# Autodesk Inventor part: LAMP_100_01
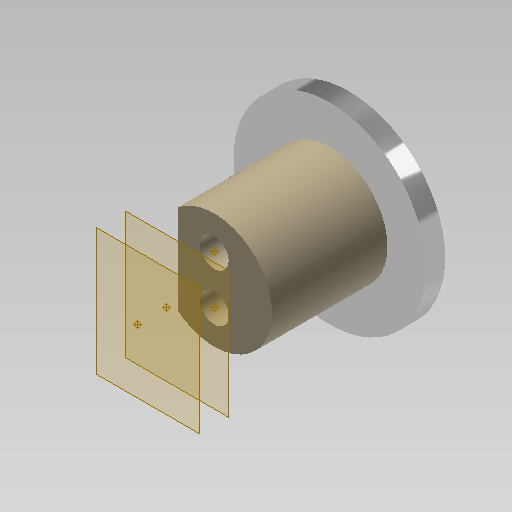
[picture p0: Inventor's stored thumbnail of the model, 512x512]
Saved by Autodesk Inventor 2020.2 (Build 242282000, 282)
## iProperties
GlobalPropertyList: <PropertyList/>
Manager: www.cadconsulting.pl
Company: Fabian Stasiak CAD Consulting
Created: 2014-09
Part Number: LAMP_100_01
Material: Ogólny
Document SubType Name: Modeling
Designer: F.Stasiak
Density: 1 g/cm^3
Appearance: Beżowa
Catalog Web Link: www.expertbooks.pl
Author: F.Stasiak
Subject: Zbiór ćwiczeń. Autodesk Inventor 2020. Kurs Professional
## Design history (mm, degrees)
sketch "Szkic1"
  geometry: C1 r 10 at (0, 0); 1 further point
  constraints: 1 centre point, 1 coincident
  dimensions: "d0" = 20 diameter of C1
extrude "Wyciągnięcie proste1" new body sketch "Szkic1" distance "d1" = 2; taper "d2" = 0 deg
sketch "Szkic2"
  geometry: C1 r 6 at (0, 0); 1 further point
  constraints: 1 centre point, 1 coincident
  dimensions: "d3" = 12 diameter of C1
extrude "Wyciągnięcie proste2" join sketch "Szkic2" distance "d4" = 12; taper "d5" = 0 deg
sketch "Szkic3"
  geometry: L1 (0, -2.5)-(0, 2.5); C1 r 1.5 at (0, -2.5); C2 r 1.5 at (0, 2.5); 2 further points
  constraints: 2 centre point, 2 end point, 1 coincident, 1 midpoint, 1 vertical
  dimensions: "d6" = 3 diameter of C1; "d7" = 3 diameter of C2; "d8" = 5 distance of L1.start L1.end
extrude "Wyciągnięcie proste3" cut sketch "Szkic3" distance "d9" = 5; taper "d10" = 0 deg
node "Płaszczyzna konstrukcyjna1"
sketch "Szkic4"
  geometry: L1 (9.27, 2)-(9.27, 0) reference; L2 (9.27, 0)-(-9.27, 0) reference; L3 (-9.27, 0)-(-9.27, 2) reference; L4 (-9.27, 2)-(-4.684, 2) reference; L5 (-4.684, 2)-(-4.684, 14) reference; L6 (-4.684, 14)-(4.684, 14) reference; L7 (4.684, 14)-(4.684, 2) reference; L8 (4.684, 2)-(9.27, 2) reference; L9 (-4.684, 8)-(4.684, 8); 1 further point
  constraints: 2 end point, 2 midpoint
extrude "Wyciągnięcie proste4" cut sketch "Szkic4" extent not by distance; stored distance "d12" = 5; taper "d13" = 0 deg
sketch "Szkic5"
  geometry: L1 (10, -2.5)-(10, 2.5); L2 (14, 4.684)-(14, -4.684) reference; C1 r 2 at (10, -2.5); C2 r 2 at (10, 2.5); 3 further points
  constraints: 2 centre point, 2 end point, 2 midpoint, 1 equal radius, 1 horizontal alignment, 1 vertical
  dimensions: "d14" = 4 diameter of C2; "d15" = 5 distance of L1.start L1.end; "d16" = 4 distance from line of L1.end L2
extrude "Wyciągnięcie proste5" cut sketch "Szkic5" distance "d17" = 0.5; taper "d18" = 0 deg
sketch "Szkic6"
  geometry: L1 (0.375, 1.56)-(-0.225, 1.56); L2 (-0.225, 1.56)-(-0.225, -1.44); L3 (-0.225, -1.44)-(0.375, -1.44); L4 (0.375, -1.44)-(0.375, 1.56); L5 (0.375, 1.56)-(-0.225, -1.44); L6 (-0.225, 1.56)-(0.375, -1.44); L7 (1.575, 0.36)-(-1.425, 0.36); L8 (-1.425, 0.36)-(-1.425, -0.24); L9 (-1.425, -0.24)-(1.575, -0.24); L10 (1.575, -0.24)-(1.575, 0.36); L11 (1.575, 0.36)-(-1.425, -0.24); L12 (-1.425, 0.36)-(1.575, -0.24); C1 r 2 at (0.075, 0.06) reference; 3 further points
  constraints: 24 end point, 5 midpoint, 4 parallel, 2 horizontal, 2 perpendicular, 1 coincident
  dimensions: "d21" = 0.6 distance of L3.end L2.end; "d22" = 3 distance of L2.end L1.end; "d19" = 3 distance of L9.end L8.end (= d22); "d20" = 0.6 distance of L8.end L7.end
extrude "Wyciągnięcie proste6" cut sketch "Szkic6" taper "d24" = -5 deg; distance "d25" = 1
mirror "Odbicie lustrzane1"
sketch "Szkic7"
  geometry: L1 (-10, 0)-(10, 0) reference; L2 (0, 0)-(0, -2.672); L3 (0, -2.672)-(2.097, -2.672); A1 r 10.839 centre (2.097, 8.167) between (2.097, -2.672) and (9.223, 0)
  constraints: 4 end point, 2 point on circle, 1 centre point, 1 perpendicular, 1 point on line, 1 tangent, 1 vertical
revolve "Obrót1" sketch "Szkic7" stored, may be unused: angle "d26" = 90 deg
sketch "Szkic8"
  geometry: C1 r 1.5 at (0, -2.5) reference
node "L1"
sketch "Szkic9"
  geometry: C1 r 1.5 at (0, 2.5) reference
node "L2"
node "Płaszczyzna konstrukcyjna2"
node "Płaszczyzna konstrukcyjna3"
node "Punkt konstrukcyjny3"
node "Punkt konstrukcyjny4"
node "Bryła1"
node "Rzutuj krawędzie tnące1"
other parameters: "d11" = -3.75, "d27" = 5, "d28" = 3
